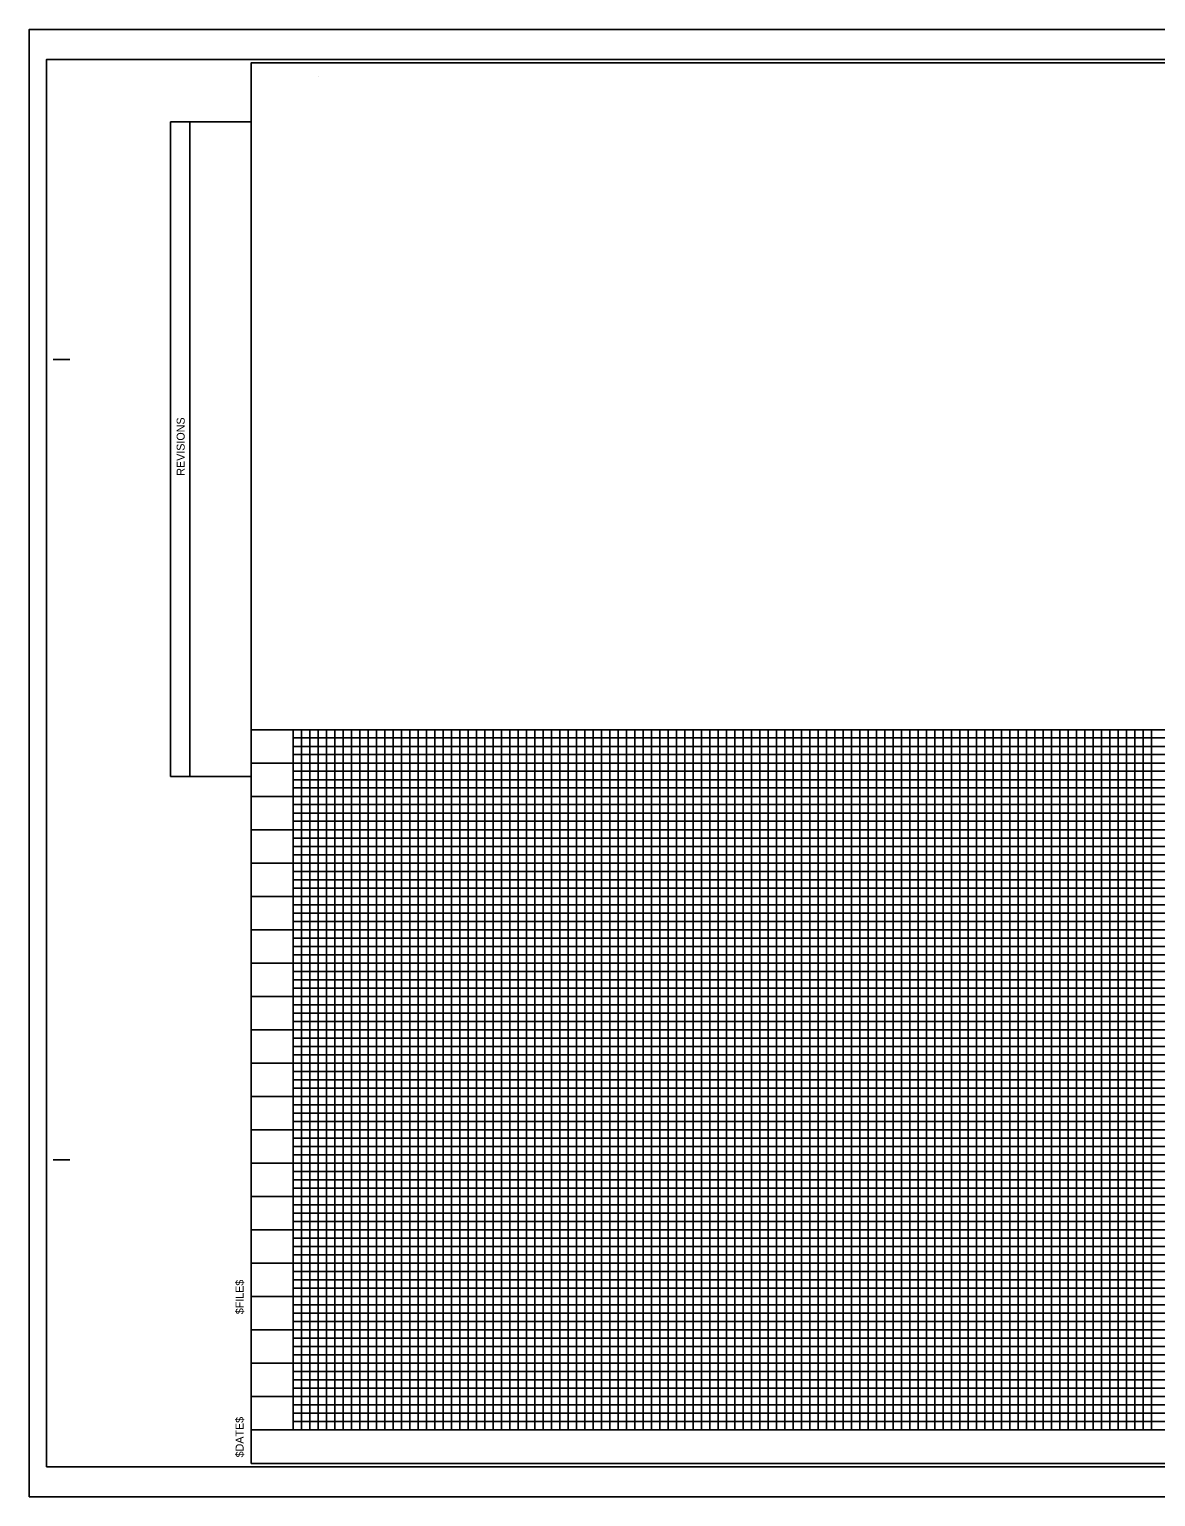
# Model space of a CAD drawing. Extents: x 2431000 to 2534000, y 645879 to 714000.
# Drawn here: x 2468411 to 2469256, y 671379 to 672479 of the extents above; entities that cross this region are included whole.
import ezdxf

# ---------------------------------------------------------------- set-up
doc = ezdxf.new("R2010")
doc.units = 0
for name, color, linetype in [('Prop Dimension', 7, 'Continuous'), ('Prop Dimension Text', 7, 'Continuous'), ('Prop Shade Light', 7, 'Continuous'), ('Prop Shade Medium', 7, 'Continuous'), ('Prop Terminator CELL', 7, 'Continuous'), ('Sheet Cross Section CELL', 7, 'Continuous'), ('Sheet Cross Section Grid Major CELL', 7, 'Continuous'), ('Sheet North Arrow Point CELL', 7, 'Continuous'), ('Sheet Plan And Profile CELL', 7, 'Continuous'), ('Sheet Plot Border Inside CELL', 7, 'Continuous')]:
    doc.layers.add(name, color=color, linetype=linetype)

msp = doc.modelspace()

# ---------------------------------------------------------------- linework, layer by layer
at = {"layer": 'Prop Dimension'}
msp.add_lwpolyline([(2468411.4, 671378.6), (2470094.9, 671378.6), (2470094.9, 672478.6), (2468411.4, 672478.6)], close=True, dxfattribs=at)
at = {"layer": 'Prop Shade Light'}
for p, q in [((2468517.4, 671918.6), (2468517.4, 672409.3)), ((2468577.9, 672409.3), (2468517.4, 672409.3)), ((2468531.9, 671918.6), (2468531.9, 672409.3)), ((2468577.9, 671918.6), (2468517.4, 671918.6))]:
    msp.add_line(p, q, dxfattribs=at)
at = {"layer": 'Prop Shade Medium'}
msp.add_line((2468577.9, 671428.6), (2468577.9, 671928.6), dxfattribs=at)
at = {"layer": 'Prop Terminator CELL'}
msp.add_lwpolyline([(2468424.4, 671401.1), (2470090.4, 671401.1), (2470090.4, 672456.1), (2468424.4, 672456.1)], close=True, dxfattribs=at)
at = {"layer": 'Sheet Cross Section CELL'}
for p, q in [((2468627.9, 672443.6), (2468627.9, 672443.6)), ((2468609.2, 671947.4), (2470046.7, 671947.4)), ((2468615.4, 671428.6), (2468615.4, 671953.6)), ((2468621.7, 671428.6), (2468621.7, 671953.6)), ((2468627.9, 671428.6), (2468627.9, 671953.6)), ((2468634.2, 671428.6), (2468634.2, 671953.6)), ((2468646.7, 671428.6), (2468646.7, 671953.6)), ((2468652.9, 671428.6), (2468652.9, 671953.6)), ((2468659.2, 671428.6), (2468659.2, 671953.6)), ((2468665.4, 671428.6), (2468665.4, 671953.6)), ((2468677.9, 671428.6), (2468677.9, 671953.6)), ((2468684.2, 671428.6), (2468684.2, 671953.6)), ((2468690.4, 671428.6), (2468690.4, 671953.6)), ((2468696.7, 671428.6), (2468696.7, 671953.6)), ((2468709.2, 671428.6), (2468709.2, 671953.6)), ((2468715.4, 671428.6), (2468715.4, 671953.6)), ((2468721.7, 671428.6), (2468721.7, 671953.6)), ((2468727.9, 671428.6), (2468727.9, 671953.6)), ((2468740.4, 671428.6), (2468740.4, 671953.6)), ((2468746.7, 671428.6), (2468746.7, 671953.6)), ((2468752.9, 671428.6), (2468752.9, 671953.6)), ((2468759.2, 671428.6), (2468759.2, 671953.6)), ((2468771.7, 671428.6), (2468771.7, 671953.6)), ((2468777.9, 671428.6), (2468777.9, 671953.6)), ((2468784.2, 671428.6), (2468784.2, 671953.6)), ((2468790.4, 671428.6), (2468790.4, 671953.6)), ((2468802.9, 671428.6), (2468802.9, 671953.6)), ((2468809.2, 671428.6), (2468809.2, 671953.6)), ((2468815.4, 671428.6), (2468815.4, 671953.6)), ((2468821.7, 671428.6), (2468821.7, 671953.6)), ((2468834.2, 671428.6), (2468834.2, 671953.6)), ((2468840.4, 671428.6), (2468840.4, 671953.6)), ((2468846.7, 671428.6), (2468846.7, 671953.6)), ((2468852.9, 671428.6), (2468852.9, 671953.6)), ((2468865.4, 671428.6), (2468865.4, 671953.6)), ((2468871.7, 671428.6), (2468871.7, 671953.6)), ((2468877.9, 671428.6), (2468877.9, 671953.6)), ((2468884.2, 671428.6), (2468884.2, 671953.6)), ((2468896.7, 671428.6), (2468896.7, 671953.6)), ((2468902.9, 671428.6), (2468902.9, 671953.6)), ((2468909.2, 671428.6), (2468909.2, 671953.6)), ((2468915.4, 671428.6), (2468915.4, 671953.6)), ((2468927.9, 671428.6), (2468927.9, 671953.6)), ((2468934.2, 671428.6), (2468934.2, 671953.6)), ((2468940.4, 671428.6), (2468940.4, 671953.6)), ((2468946.7, 671428.6), (2468946.7, 671953.6)), ((2468959.2, 671428.6), (2468959.2, 671953.6)), ((2468965.4, 671428.6), (2468965.4, 671953.6)), ((2468971.7, 671428.6), (2468971.7, 671953.6)), ((2468977.9, 671428.6), (2468977.9, 671953.6)), ((2468990.4, 671428.6), (2468990.4, 671953.6)), ((2468996.7, 671428.6), (2468996.7, 671953.6)), ((2469002.9, 671428.6), (2469002.9, 671953.6)), ((2469009.2, 671428.6), (2469009.2, 671953.6)), ((2469021.7, 671428.6), (2469021.7, 671953.6)), ((2469027.9, 671428.6), (2469027.9, 671953.6)), ((2469034.2, 671428.6), (2469034.2, 671953.6)), ((2469040.4, 671428.6), (2469040.4, 671953.6)), ((2469052.9, 671428.6), (2469052.9, 671953.6)), ((2469059.2, 671428.6), (2469059.2, 671953.6)), ((2469065.4, 671428.6), (2469065.4, 671953.6)), ((2469071.7, 671428.6), (2469071.7, 671953.6)), ((2469084.2, 671428.6), (2469084.2, 671953.6)), ((2469090.4, 671428.6), (2469090.4, 671953.6)), ((2469096.7, 671428.6), (2469096.7, 671953.6)), ((2469102.9, 671428.6), (2469102.9, 671953.6)), ((2469115.4, 671428.6), (2469115.4, 671953.6)), ((2469121.7, 671428.6), (2469121.7, 671953.6)), ((2469127.9, 671428.6), (2469127.9, 671953.6)), ((2469134.2, 671428.6), (2469134.2, 671953.6)), ((2469146.7, 671428.6), (2469146.7, 671953.6)), ((2469152.9, 671428.6), (2469152.9, 671953.6)), ((2469159.2, 671428.6), (2469159.2, 671953.6)), ((2469165.4, 671428.6), (2469165.4, 671953.6)), ((2469177.9, 671428.6), (2469177.9, 671953.6)), ((2469184.2, 671428.6), (2469184.2, 671953.6)), ((2469190.4, 671428.6), (2469190.4, 671953.6)), ((2469196.7, 671428.6), (2469196.7, 671953.6)), ((2469209.2, 671428.6), (2469209.2, 671953.6)), ((2469215.4, 671428.6), (2469215.4, 671953.6)), ((2469221.7, 671428.6), (2469221.7, 671953.6)), ((2469227.9, 671428.6), (2469227.9, 671953.6)), ((2469240.4, 671428.6), (2469240.4, 671953.6)), ((2469246.7, 671428.6), (2469246.7, 671953.6)), ((2469252.9, 671428.6), (2469252.9, 671953.6)), ((2468609.2, 671941.1), (2470046.7, 671941.1)), ((2468609.2, 671934.9), (2470046.7, 671934.9)), ((2468609.2, 671922.4), (2470046.7, 671922.4)), ((2468609.2, 671916.1), (2470046.7, 671916.1)), ((2468609.2, 671909.9), (2470046.7, 671909.9)), ((2468609.2, 671897.4), (2470046.7, 671897.4)), ((2468609.2, 671891.1), (2470046.7, 671891.1)), ((2468609.2, 671884.9), (2470046.7, 671884.9)), ((2468609.2, 671872.4), (2470046.7, 671872.4)), ((2468609.2, 671866.1), (2470046.7, 671866.1)), ((2468609.2, 671859.9), (2470046.7, 671859.9)), ((2468609.2, 671847.4), (2470046.7, 671847.4)), ((2468609.2, 671841.1), (2470046.7, 671841.1)), ((2468609.2, 671834.9), (2470046.7, 671834.9)), ((2468609.2, 671822.4), (2470046.7, 671822.4)), ((2468609.2, 671816.1), (2470046.7, 671816.1)), ((2468609.2, 671809.9), (2470046.7, 671809.9)), ((2468609.2, 671797.4), (2470046.7, 671797.4)), ((2468609.2, 671791.1), (2470046.7, 671791.1)), ((2468609.2, 671784.9), (2470046.7, 671784.9)), ((2468609.2, 671772.4), (2470046.7, 671772.4)), ((2468609.2, 671766.1), (2470046.7, 671766.1)), ((2468609.2, 671759.9), (2470046.7, 671759.9)), ((2468609.2, 671747.4), (2470046.7, 671747.4)), ((2468609.2, 671741.1), (2470046.7, 671741.1)), ((2468609.2, 671734.9), (2470046.7, 671734.9)), ((2468609.2, 671722.4), (2470046.7, 671722.4)), ((2468609.2, 671716.1), (2470046.7, 671716.1)), ((2468609.2, 671709.9), (2470046.7, 671709.9)), ((2468609.2, 671697.4), (2470046.7, 671697.4)), ((2468609.2, 671691.1), (2470046.7, 671691.1)), ((2468609.2, 671684.9), (2470046.7, 671684.9)), ((2468609.2, 671672.4), (2470046.7, 671672.4)), ((2468609.2, 671666.1), (2470046.7, 671666.1)), ((2468609.2, 671659.9), (2470046.7, 671659.9)), ((2468609.2, 671647.4), (2470046.7, 671647.4)), ((2468609.2, 671641.1), (2470046.7, 671641.1)), ((2468609.2, 671634.9), (2470046.7, 671634.9)), ((2468609.2, 671622.4), (2470046.7, 671622.4)), ((2468609.2, 671616.1), (2470046.7, 671616.1)), ((2468609.2, 671609.9), (2470046.7, 671609.9)), ((2468609.2, 671597.4), (2470046.7, 671597.4)), ((2468609.2, 671591.1), (2470046.7, 671591.1)), ((2468609.2, 671584.9), (2470046.7, 671584.9)), ((2468609.2, 671572.4), (2470046.7, 671572.4)), ((2468609.2, 671566.1), (2470046.7, 671566.1)), ((2468609.2, 671559.9), (2470046.7, 671559.9)), ((2468609.2, 671547.4), (2470046.7, 671547.4)), ((2468609.2, 671541.1), (2470046.7, 671541.1)), ((2468609.2, 671534.9), (2470046.7, 671534.9)), ((2468609.2, 671522.4), (2470046.7, 671522.4)), ((2468609.2, 671516.1), (2470046.7, 671516.1)), ((2468609.2, 671509.9), (2470046.7, 671509.9)), ((2468609.2, 671497.4), (2470046.7, 671497.4)), ((2468609.2, 671491.1), (2470046.7, 671491.1)), ((2468609.2, 671484.9), (2470046.7, 671484.9)), ((2468609.2, 671472.4), (2470046.7, 671472.4)), ((2468609.2, 671466.1), (2470046.7, 671466.1)), ((2468609.2, 671459.9), (2470046.7, 671459.9)), ((2468609.2, 671447.4), (2470046.7, 671447.4)), ((2468609.2, 671441.1), (2470046.7, 671441.1)), ((2468609.2, 671434.9), (2470046.7, 671434.9))]:
    msp.add_line(p, q, dxfattribs=at)
at = {"layer": 'Sheet Cross Section Grid Major CELL'}
for p, q in [((2468640.4, 671428.6), (2468640.4, 671953.6)), ((2468702.9, 671428.6), (2468702.9, 671953.6)), ((2468765.4, 671428.6), (2468765.4, 671953.6)), ((2468827.9, 671428.6), (2468827.9, 671953.6)), ((2468890.4, 671428.6), (2468890.4, 671953.6)), ((2468952.9, 671428.6), (2468952.9, 671953.6)), ((2469015.4, 671428.6), (2469015.4, 671953.6)), ((2469077.9, 671428.6), (2469077.9, 671953.6)), ((2469140.4, 671428.6), (2469140.4, 671953.6)), ((2469202.9, 671428.6), (2469202.9, 671953.6)), ((2468577.9, 671928.6), (2470077.9, 671928.6)), ((2468577.9, 671878.6), (2470077.9, 671878.6)), ((2468577.9, 671828.6), (2470077.9, 671828.6)), ((2468577.9, 671778.6), (2470077.9, 671778.6)), ((2468577.9, 671728.6), (2470077.9, 671728.6)), ((2468577.9, 671678.6), (2470077.9, 671678.6)), ((2468577.9, 671628.6), (2470077.9, 671628.6)), ((2468577.9, 671578.6), (2470077.9, 671578.6)), ((2468577.9, 671528.6), (2470077.9, 671528.6)), ((2468577.9, 671478.6), (2470077.9, 671478.6))]:
    msp.add_line(p, q, dxfattribs=at)
at = {"layer": 'Sheet North Arrow Point CELL'}
for p, q in [((2468577.9, 671953.6), (2470077.9, 671953.6)), ((2468609.2, 671953.6), (2468609.2, 671428.6)), ((2468671.7, 671428.6), (2468671.7, 671953.6)), ((2468734.2, 671428.6), (2468734.2, 671953.6)), ((2468796.7, 671428.6), (2468796.7, 671953.6)), ((2468859.2, 671428.6), (2468859.2, 671953.6)), ((2468921.7, 671428.6), (2468921.7, 671953.6)), ((2468984.2, 671428.6), (2468984.2, 671953.6)), ((2469046.7, 671428.6), (2469046.7, 671953.6)), ((2469109.2, 671428.6), (2469109.2, 671953.6)), ((2469171.7, 671428.6), (2469171.7, 671953.6)), ((2469234.2, 671428.6), (2469234.2, 671953.6)), ((2468577.9, 671903.6), (2470077.9, 671903.6)), ((2468577.9, 671853.6), (2470077.9, 671853.6)), ((2468577.9, 671803.6), (2470077.9, 671803.6)), ((2468577.9, 671753.6), (2470077.9, 671753.6)), ((2468577.9, 671703.6), (2470077.9, 671703.6)), ((2468577.9, 671653.6), (2470077.9, 671653.6)), ((2468577.9, 671603.6), (2470077.9, 671603.6)), ((2468577.9, 671553.6), (2470077.9, 671553.6)), ((2468577.9, 671503.6), (2470077.9, 671503.6)), ((2468577.9, 671453.6), (2470077.9, 671453.6)), ((2468577.9, 671428.6), (2468577.9, 671428.6))]:
    msp.add_line(p, q, dxfattribs=at)
for points in [[(2470046.7, 671953.6), (2470046.7, 671428.6), (2468609.2, 671428.6), (2468609.2, 671953.6)], [(2470077.9, 671428.6), (2468577.9, 671428.6)]]:
    msp.add_lwpolyline(points, dxfattribs=at)
at = {"layer": 'Sheet Plan And Profile CELL'}
for p, q in [((2468429.4, 672231.1), (2468441.9, 672231.1)), ((2468429.4, 671631.1), (2468441.9, 671631.1)), ((2470077.9, 671428.6), (2468577.9, 671428.6)), ((2468577.9, 671403.6), (2470077.9, 671403.6)), ((2468577.9, 671403.6), (2468577.9, 671403.6)), ((2468577.9, 671403.6), (2468577.9, 671403.6)), ((2468577.9, 671403.6), (2468577.9, 671403.6)), ((2468577.9, 671403.6), (2468577.9, 671403.6)), ((2468577.9, 671403.6), (2468577.9, 671403.6)), ((2468577.9, 671403.6), (2468577.9, 671403.6)), ((2468577.9, 671403.6), (2468577.9, 671403.6))]:
    msp.add_line(p, q, dxfattribs=at)
msp.add_lwpolyline([(2470077.9, 672453.6), (2468577.9, 672453.6), (2468577.9, 671403.6), (2470077.9, 671403.6)], close=True, dxfattribs=at)
msp.add_lwpolyline([(2468615.4, 671403.6), (2468615.4, 671403.6)], dxfattribs=at)
at = {"layer": 'Sheet Plot Border Inside CELL'}
msp.add_line((2468609.2, 671428.6), (2468609.2, 671853.6), dxfattribs=at)

# ---------------------------------------------------------------- texts
at = {"layer": 'Prop Dimension Text'}
for s, p in [('$FILE$', (2468572.1, 671515.4)), ('$DATE$', (2468572.1, 671408.1))]:
    msp.add_text(s, height=6, rotation=90, dxfattribs=at).set_placement(p)
at = {"layer": 'Prop Shade Light'}
msp.add_text('REVISIONS', height=6, rotation=90, dxfattribs=at).set_placement((2468527.9, 672144))

doc.saveas('drawing.dxf')
